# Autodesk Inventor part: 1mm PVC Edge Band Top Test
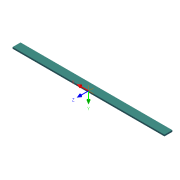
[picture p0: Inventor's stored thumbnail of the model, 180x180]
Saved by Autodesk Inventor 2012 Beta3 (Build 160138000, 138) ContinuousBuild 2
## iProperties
Created: 2011-02
Part Number: 1mm PVC Edge Band Top Test
Material: Default
Document SubType Name: Modeling
Designer: Beta-8540w
Density: 1 g/cm^3
d0: 16.000 in
d2: 0.039 in
Author: Beta-8540w
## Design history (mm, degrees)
sketch "Sketch1"
  geometry: L1 (-203.2, 7.938)-(203.2, 7.938); L2 (203.2, 7.938)-(203.2, -7.938); L3 (203.2, -7.938)-(-203.2, -7.938); L4 (-203.2, -7.938)-(-203.2, 7.938); 3 further points
  constraints: 8 end point, 2 midpoint, 2 parallel, 1 horizontal, 1 horizontal alignment, 1 perpendicular, 1 vertical alignment
  dimensions: "d0" = 406.4 distance of L1.start L1.end (= drawer_width); "d1" = 15.875 distance of L1.end L2.end
extrude "Extrusion1" new body sketch "Sketch1" distance "d2" = 1 (= edge_band_thickness); taper "d3" = 0 deg
body "Solid1"
other parameters: "d4" = 0, "d5" = 0, "d6" = 0, "d7" = 0, "d8" = 0, "d9" = 0, "drawer_width" = 406.4, "edge_band_thickness" = 1
